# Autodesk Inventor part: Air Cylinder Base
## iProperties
Created: 2010-01
Part Number: Air Cylinder Base
Document SubType Name: Modeling
Designer: cmcfadden
Density: 1 g/cm^3
Author: cmcfadden
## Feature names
1. Extrusion1
